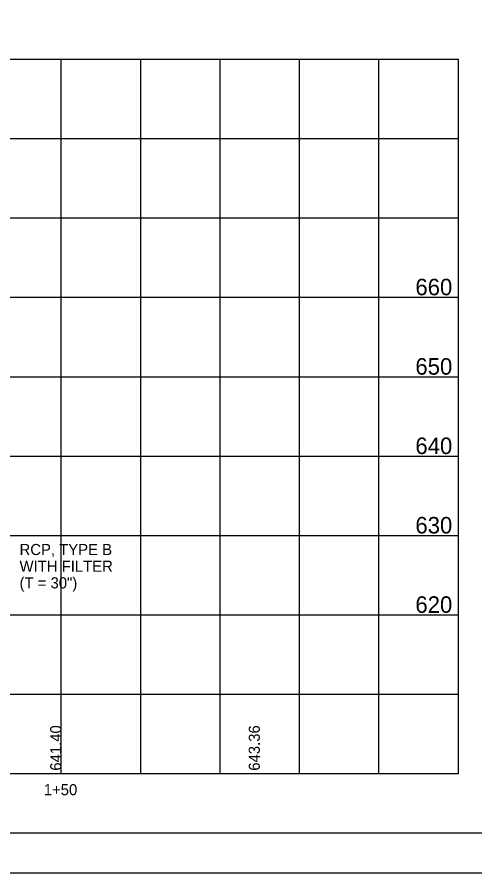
# Model space of a CAD drawing. Extents: x 0 to 340, y 0 to 220.
# Drawn here: x 166.9 to 224.6, y 0 to 107.8 of the extents above; entities that cross this region are included whole.
import ezdxf

# ---------------------------------------------------------------- set-up
doc = ezdxf.new("R2010")
doc.units = 0
for name, color, linetype in [('Default', 7, 'Continuous'), ('GE_P_Alignment_100_Stations', 7, 'Continuous'), ('GE_X_Alignment_100_Stations', 7, 'Continuous'), ('MT_P_Work_Area', 7, 'Continuous'), ('PV_P_EOP', 7, 'Continuous'), ('PV_P_Shoulder', 7, 'Continuous'), ('SH_Named_Boundary', 7, 'Continuous')]:
    doc.layers.add(name, color=color, linetype=linetype)

msp = doc.modelspace()

# ---------------------------------------------------------------- linework, layer by layer
at = {"layer": 'GE_X_Alignment_100_Stations'}
msp.add_lwpolyline([(15, 215), (335, 215), (335, 5), (15, 5)], close=True, dxfattribs=at)
at = {"layer": 'PV_P_EOP'}
for p, q in [((22.5, 102.5), (222.5, 102.5)), ((222.5, 12.5), (222.5, 102.5)), ((22.5, 12.5), (222.5, 12.5))]:
    msp.add_line(p, q, dxfattribs=at)
at = {"layer": 'PV_P_Shoulder'}
for p, q in [((172.5, 12.5), (172.5, 102.5)), ((182.5, 12.5), (182.5, 102.5)), ((192.5, 12.5), (192.5, 102.5)), ((202.5, 12.5), (202.5, 102.5)), ((212.5, 12.5), (212.5, 102.5)), ((222.5, 12.5), (222.5, 102.5)), ((22.5, 92.5), (222.5, 92.5)), ((22.5, 82.5), (222.5, 82.5)), ((22.5, 72.5), (222.5, 72.5)), ((22.5, 62.5), (222.5, 62.5)), ((22.5, 52.5), (222.5, 52.5)), ((22.5, 42.5), (222.5, 42.5)), ((22.5, 32.5), (222.5, 32.5)), ((22.5, 22.5), (222.5, 22.5))]:
    msp.add_line(p, q, dxfattribs=at)
at = {"layer": 'SH_Named_Boundary'}
msp.add_lwpolyline([(0, 0), (340, 0), (340, 220), (0, 220)], close=True, dxfattribs=at)

# ---------------------------------------------------------------- texts
at = {"layer": 'Default'}
for s, p in [('660', (217.09, 72.75)), ('650', (217.09, 62.75)), ('640', (217.09, 52.75)), ('630', (217.09, 42.75)), ('620', (217.09, 32.75))]:
    msp.add_text(s, height=2.083, dxfattribs=at).set_placement(p)
at = {"layer": 'GE_P_Alignment_100_Stations'}
for s, p in [('641.40', (172.5, 12.87)), ('643.36', (197.5, 12.87))]:
    msp.add_text(s, height=1.4, rotation=90, dxfattribs=at).set_placement(p)
msp.add_text('1+50', height=1.4, dxfattribs=at).set_placement((170.29, 9.78))
at = {"layer": 'MT_P_Work_Area'}
for s, p in [('RCP, TYPE B', (167.24, 40.03)), ('WITH FILTER', (167.24, 37.93)), ('(T = 30")', (167.24, 35.83))]:
    msp.add_text(s, height=1.4, dxfattribs=at).set_placement(p)

doc.saveas('drawing.dxf')
